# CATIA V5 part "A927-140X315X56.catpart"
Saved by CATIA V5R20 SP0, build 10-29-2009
Part number: A927-140X315X56
Source: Unknown
Property "A": "90.000"
Property "ARTICLENO": "A927-140X315X56"
Property "BOMINFO": "A927-140X315X56"
Property "CODE": "A927-140X315X56"
Property "CREATOR": "CADENAS GmbH"
Property "D": "22.000"
Property "D1": "33.000"
Property "F": "36.000"
Property "FORM": "B"
Property "L": "315.000"
Property "L1": "150.000"
Property "L2": "40.000"
Property "L3": "80.000"
Property "LINA": "A927-140X315X56"
Property "NB": "A927-140X315X56"
Property "NBSYN": "$CODE."
Property "NN": "A927"
Property "NT": "VDI 3387 Removable Die Heels, steel and self-lubricating"
Property "R": "31.500"
Property "S": "56.000"
Property "SUPPLIER": "CF"
Property "T": "25.500"
Property "W": "140.000"
Bounding box of the stored display mesh (mm): x -70 to 70, y 0 to 315, z -56 to 0
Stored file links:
  C:\Users\borellobunino\Desktop\3D X SITO CF\A927\GSB_OILLESS_G2290514031556\CATIAV5\A927-140X315X56.catpart
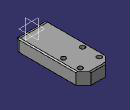
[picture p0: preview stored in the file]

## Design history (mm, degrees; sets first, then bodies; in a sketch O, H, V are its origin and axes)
Body1 "Geometry.1" (main body)
  Solid1 "A927-140X315X56.catpart": solid without history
